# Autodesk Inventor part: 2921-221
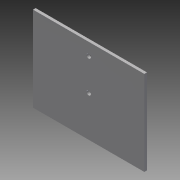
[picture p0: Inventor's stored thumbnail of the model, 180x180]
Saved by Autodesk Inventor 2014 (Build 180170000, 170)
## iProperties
Company: NHTSA/VRTC
Created: 2012-08
Part Number: 2921-221
Material: Steel, Mild
Document SubType Name: Modeling
Designer: Mike Vanvoorhis
Density: 7.86 g/cm^3
Mass: 9128.86 g
Surface Area: 2572.98 cm^2
Volume: 1161.43 cm^3
Project: CHILD SIDE IMPACT SLED
Description: IMPACTOR STOP FACE PLATE
Stock Number: PL 9.5 (3/8") x 304.8 (12") x 400.1 (15 3/4")
Appearance: Steel
Author: Dave Walker
Title: Impactor Stop Face Plate
Subject: Child Side Impact sled
Revision Number: A
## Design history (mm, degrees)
sketch "Sketch1"
  geometry: L1 (0, 0)-(400.05, 0); L2 (400.05, 0)-(400.05, 304.8); L3 (400.05, 304.8)-(0, 304.8); L4 (0, 304.8)-(0, 0)
  constraints: 8 end point, 2 parallel, 1 horizontal, 1 perpendicular
  dimensions: "d0" = 400.05 distance of L3.end L2.end; "d1" = 304.8 distance of L2.end L1.end
extrude "Extrusion1" new body sketch "Sketch1" distance "d2" = 9.525; taper "d3" = 0 deg
sketch "Sketch2"
  geometry: L1 (400.05, 304.8)-(0, 304.8) reference; L2 (0, 304.8)-(0, 0) reference; L3 (200.025, 304.8)-(200.025, 260.35); L4 (200.025, 260.35)-(200.025, 146.05)
  constraints: 4 end point, 1 collinear, 1 midpoint, 1 parallel
  dimensions: "d4" = 44.45 distance of L3.start L3.end; "d5" = 114.3 distance of L3.end L4.end
hole "Hole1" sketch "Sketch2" at (200.025, 260.35), (200.025, 146.05) diameter "d6" = 15.875; stored, may be unused: countersink angle "d10" = 82 deg, drill point angle "d12" = 118 deg; dims "d7" = 19.05, "d8" = 9.525, "d9" = 6.35, "d11" = 25.4
body "Solid1"
